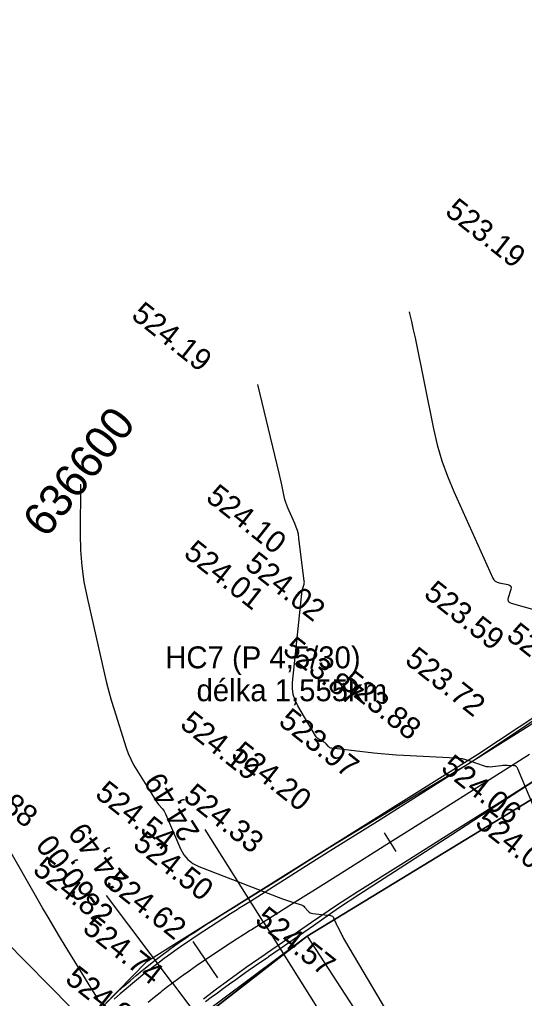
# Model space of a CAD drawing. Extents: x -636600 to -628587, y -1090963 to -1085869.
# Drawn here: x -629781.6 to -629735.5, y -1089769.7 to -1089680.4 of the extents above; entities that cross this region are included whole.
import ezdxf

# ---------------------------------------------------------------- set-up
doc = ezdxf.new("R2010")
doc.units = 0
for name, color, linetype in [('01_PARCELY_NÁVRH_PC', 7, 'Continuous'), ('21', 7, 'Continuous'), ('23', 7, 'Continuous'), ('Ex_Major Contours', 7, 'Continuous'), ('Ex_Minor Contours', 7, 'Continuous'), ('HEKTOMETRY100', 7, 'Continuous'), ('HEKTOMETRY20', 7, 'Continuous'), ('HL_BODY', 7, 'Continuous'), ('koty_vše', 7, 'Continuous'), ('PARCELY_NÁVRH_SILNICE_ŽELEZNICE', 7, 'Continuous'), ('POLOMERY', 7, 'Continuous'), ('popis', 7, 'Continuous'), ('situace_osa', 7, 'Continuous'), ('situace_těleso', 7, 'Continuous'), ('situace_vozovka', 7, 'Continuous'), ('síť křížků', 7, 'Continuous'), ('VRCHOLY', 7, 'Continuous')]:
    doc.layers.add(name, color=color, linetype=linetype)

msp = doc.modelspace()

# ---------------------------------------------------------------- linework, layer by layer
at = {"layer": '01_PARCELY_NÁVRH_PC'}
msp.add_lwpolyline([(-629647.363, -1089680.417), (-629666.288, -1089692.668), (-629711.76, -1089728.929), (-629739.767, -1089747.431), (-629770.066, -1089766.37), (-629781.624, -1089778.209), (-629800.275, -1089807.802), (-629798.048, -1089809.483), (-629791.307, -1089814.356), (-629789.014, -1089815.993), (-629775.661, -1089789.328), (-629773.774, -1089778.258), (-629755.349, -1089764.02), (-629715.944, -1089740.02), (-629693.039, -1089722.565), (-629669.229, -1089703.189), (-629636.498, -1089682.368)], dxfattribs=at)
at = {"layer": '21'}
for p, q in [((-629715.944, -1089740.02), (-629755.349, -1089764.02)), ((-629755.349, -1089764.02), (-629773.469, -1089777.492))]:
    msp.add_line(p, q, dxfattribs=at)
at = {"layer": '23'}
for p, q in [((-629773.774, -1089778.258), (-629755.349, -1089764.02)), ((-629755.349, -1089764.02), (-629745.662, -1089778.847))]:
    msp.add_line(p, q, dxfattribs=at)
at = {"layer": 'Ex_Major Contours'}
msp.add_lwpolyline([(-629774.482, -1089769.733), (-629777.454, -1089764.884), (-629777.978, -1089764.022), (-629778.495, -1089763.156), (-629779.006, -1089762.286), (-629779.51, -1089761.412), (-629783.136, -1089755.074)], dxfattribs=at)
at = {"layer": 'Ex_Minor Contours'}
for points in [[(-629746.032, -1089707.072), (-629746, -1089707.207), (-629745.83, -1089707.954), (-629745.667, -1089708.703), (-629745.51, -1089709.453), (-629743.818, -1089717.743), (-629743.476, -1089719.211), (-629743.053, -1089720.652), (-629742.551, -1089722.068), (-629741.97, -1089723.458), (-629738.405, -1089731.35), (-629738.307, -1089731.516), (-629738.181, -1089731.645), (-629738.025, -1089731.737), (-629737.84, -1089731.792), (-629737.034, -1089731.941), (-629736.871, -1089731.996), (-629736.772, -1089732.089), (-629736.737, -1089732.22), (-629736.766, -1089732.389), (-629737.008, -1089733.142), (-629737.037, -1089733.313), (-629737.004, -1089733.451), (-629736.907, -1089733.555), (-629736.748, -1089733.625), (-629729.613, -1089735.629)], [(-629734.308, -1089753.082), (-629736.118, -1089748.738), (-629736.183, -1089748.622), (-629736.271, -1089748.538), (-629736.38, -1089748.485), (-629736.511, -1089748.463), (-629737.079, -1089748.438), (-629737.221, -1089748.435), (-629737.363, -1089748.438), (-629737.504, -1089748.447), (-629737.645, -1089748.463), (-629738.45, -1089748.571), (-629738.631, -1089748.585), (-629738.808, -1089748.578), (-629738.984, -1089748.55), (-629739.158, -1089748.5), (-629740.577, -1089748.007), (-629740.873, -1089747.915), (-629741.173, -1089747.846), (-629741.478, -1089747.797), (-629741.787, -1089747.771), (-629746.565, -1089747.53), (-629747.241, -1089747.491), (-629747.915, -1089747.441), (-629748.589, -1089747.38), (-629749.262, -1089747.308), (-629753.128, -1089746.866), (-629753.209, -1089746.85), (-629753.282, -1089746.82), (-629753.349, -1089746.777), (-629753.409, -1089746.721), (-629753.634, -1089746.469), (-629753.692, -1089746.409), (-629753.755, -1089746.354), (-629753.822, -1089746.304), (-629753.893, -1089746.26), (-629754.293, -1089746.032), (-629754.379, -1089745.975), (-629754.456, -1089745.909), (-629754.524, -1089745.833), (-629754.582, -1089745.747), (-629756.216, -1089742.987), (-629756.463, -1089742.488), (-629756.623, -1089741.969), (-629756.696, -1089741.431), (-629756.682, -1089740.874), (-629755.856, -1089732.75), (-629755.843, -1089732.654), (-629755.826, -1089732.558), (-629755.804, -1089732.463), (-629755.776, -1089732.37), (-629755.657, -1089731.998), (-629755.632, -1089731.904), (-629755.618, -1089731.81), (-629755.614, -1089731.714), (-629755.621, -1089731.618), (-629756.105, -1089727.702), (-629756.161, -1089727.358), (-629756.241, -1089727.022), (-629756.348, -1089726.692), (-629756.479, -1089726.369), (-629757.119, -1089724.953), (-629757.224, -1089724.701), (-629757.315, -1089724.445), (-629757.391, -1089724.184), (-629757.453, -1089723.918), (-629757.672, -1089722.847), (-629757.728, -1089722.579), (-629757.786, -1089722.312), (-629757.847, -1089722.046), (-629757.91, -1089721.78), (-629759.86, -1089713.707)], [(-629776.041, -1089722.79), (-629776.079, -1089727.338), (-629776.049, -1089728.8), (-629775.934, -1089730.253), (-629775.736, -1089731.696), (-629775.453, -1089733.13), (-629773.865, -1089740.124), (-629773.676, -1089740.915), (-629773.471, -1089741.7), (-629773.249, -1089742.482), (-629773.01, -1089743.258), (-629771.875, -1089746.816), (-629771.685, -1089747.353), (-629771.462, -1089747.874), (-629771.208, -1089748.381), (-629770.921, -1089748.873), (-629769.245, -1089751.552), (-629769.172, -1089751.664), (-629769.095, -1089751.773), (-629769.014, -1089751.88), (-629768.929, -1089751.983), (-629768.58, -1089752.39), (-629768.497, -1089752.495), (-629768.423, -1089752.604), (-629768.357, -1089752.72), (-629768.3, -1089752.84), (-629766.918, -1089756.044), (-629766.628, -1089756.576), (-629766.254, -1089757.02), (-629765.795, -1089757.377), (-629765.254, -1089757.647), (-629757.623, -1089760.604), (-629757.44, -1089760.673), (-629757.255, -1089760.737), (-629757.069, -1089760.798), (-629756.881, -1089760.854), (-629755.986, -1089761.112), (-629755.872, -1089761.153), (-629755.768, -1089761.209), (-629755.673, -1089761.279), (-629755.587, -1089761.363), (-629755.26, -1089761.728), (-629755.174, -1089761.81), (-629755.077, -1089761.872), (-629754.97, -1089761.915), (-629754.854, -1089761.938), (-629753.221, -1089762.125), (-629753.131, -1089762.146), (-629753.055, -1089762.187), (-629752.993, -1089762.248), (-629752.947, -1089762.328), (-629752.789, -1089762.688), (-629752.749, -1089762.778), (-629752.708, -1089762.868), (-629752.666, -1089762.957), (-629752.624, -1089763.046), (-629752.267, -1089763.779), (-629752.191, -1089763.929), (-629752.113, -1089764.079), (-629752.032, -1089764.226), (-629751.947, -1089764.372), (-629745.083, -1089775.97)]]:
    msp.add_lwpolyline(points, dxfattribs=at)
at = {"layer": 'HEKTOMETRY100'}
msp.add_lwpolyline([(-629763.521, -1089767.807), (-629765.762, -1089764.494)], dxfattribs=at)
at = {"layer": 'HEKTOMETRY20'}
msp.add_lwpolyline([(-629747.22, -1089756.284), (-629748.286, -1089754.592)], dxfattribs=at)
at = {"layer": 'HL_BODY'}
for points in [[(-629759.344, -1089762.734), (-629754.017, -1089771.197)], [(-629767.653, -1089768.292), (-629761.641, -1089776.282)]]:
    msp.add_lwpolyline(points, dxfattribs=at)
at = {"layer": 'PARCELY_NÁVRH_SILNICE_ŽELEZNICE'}
msp.add_lwpolyline([(-629636.498, -1089682.368), (-629669.229, -1089703.189), (-629693.039, -1089722.565), (-629715.944, -1089740.02), (-629755.349, -1089764.02), (-629773.774, -1089778.258), (-629775.661, -1089789.328), (-629789.014, -1089815.993), (-629763.271, -1089834.375), (-629762.496, -1089834.892), (-629746.798, -1089807.362), (-629739.641, -1089797.354), (-629724.72, -1089773.793), (-629704.711, -1089750.564), (-629683.036, -1089730.713), (-629659.95, -1089713.109)], dxfattribs=at)
at = {"layer": 'POLOMERY'}
for points in [[(-629759.344, -1089762.734), (-629764.671, -1089754.271)], [(-629767.653, -1089768.292), (-629773.666, -1089760.302)]]:
    msp.add_lwpolyline(points, dxfattribs=at)
at = {"layer": 'situace_osa'}
msp.add_lwpolyline([(-629735.058, -1089747.448), (-629739.29, -1089750.111), (-629743.521, -1089752.775), (-629747.753, -1089755.438), (-629751.984, -1089758.101), (-629753.876, -1089759.292), (-629756.216, -1089760.765), (-629759.344, -1089762.734), (-629759.949, -1089763.115), (-629760.447, -1089763.429), (-629760.553, -1089763.496), (-629761.156, -1089763.878), (-629761.759, -1089764.261), (-629762.36, -1089764.647), (-629762.959, -1089765.035), (-629763.557, -1089765.427), (-629764.152, -1089765.822), (-629764.641, -1089766.15), (-629764.745, -1089766.22), (-629765.334, -1089766.624), (-629765.92, -1089767.032), (-629766.476, -1089767.427), (-629766.502, -1089767.446), (-629767.08, -1089767.866), (-629767.653, -1089768.292), (-629768.218, -1089768.722), (-629768.687, -1089769.087), (-629768.778, -1089769.159), (-629769.332, -1089769.603), (-629769.881, -1089770.053)], dxfattribs=at)
at = {"layer": 'situace_těleso'}
for points in [[(-629773.694, -1089770.086), (-629773.174, -1089769.559), (-629772.637, -1089769.049), (-629772.09, -1089768.55), (-629771.53, -1089768.065), (-629770.965, -1089767.587), (-629770.393, -1089767.115), (-629770.299, -1089767.039), (-629769.815, -1089766.651), (-629769.232, -1089766.195), (-629768.64, -1089765.743), (-629768.044, -1089765.301), (-629768.017, -1089765.281), (-629767.445, -1089764.866), (-629766.841, -1089764.442), (-629766.231, -1089764.031), (-629766.124, -1089763.959), (-629765.619, -1089763.626), (-629765.007, -1089763.227), (-629764.393, -1089762.833), (-629763.78, -1089762.444), (-629763.166, -1089762.059), (-629762.555, -1089761.675), (-629761.944, -1089761.294), (-629761.837, -1089761.228), (-629761.334, -1089760.916), (-629760.725, -1089760.54), (-629757.578, -1089758.601), (-629755.243, -1089757.12), (-629753.355, -1089755.924), (-629749.074, -1089753.34), (-629744.787, -1089750.764), (-629740.493, -1089748.199), (-629736.33, -1089745.428), (-629732.185, -1089742.626)], [(-629733.851, -1089749.366), (-629738.042, -1089752.093), (-629742.234, -1089754.82), (-629746.431, -1089757.538), (-629750.634, -1089760.248), (-629752.507, -1089761.466), (-629754.767, -1089763.067), (-629757.812, -1089765.169), (-629758.401, -1089765.57), (-629758.886, -1089765.901), (-629758.989, -1089765.971), (-629759.573, -1089766.371), (-629760.155, -1089766.771), (-629760.733, -1089767.172), (-629761.307, -1089767.573), (-629761.877, -1089767.976), (-629762.443, -1089768.38), (-629762.906, -1089768.716), (-629763.003, -1089768.787), (-629763.559, -1089769.195), (-629764.108, -1089769.607), (-629764.627, -1089770.003)]]:
    msp.add_lwpolyline(points, dxfattribs=at)
at = {"layer": 'situace_vozovka'}
for points in [[(-629732.025, -1089742.88), (-629736.257, -1089745.543), (-629740.488, -1089748.207), (-629744.72, -1089750.87), (-629748.951, -1089753.534), (-629753.183, -1089756.197), (-629755.075, -1089757.388), (-629757.415, -1089758.861), (-629760.543, -1089760.83), (-629761.148, -1089761.211), (-629761.648, -1089761.526), (-629761.755, -1089761.593), (-629762.362, -1089761.978), (-629762.97, -1089762.365), (-629763.579, -1089762.756), (-629764.187, -1089763.15), (-629764.795, -1089763.548), (-629765.402, -1089763.951), (-629765.902, -1089764.287), (-629766.008, -1089764.359), (-629766.613, -1089764.772), (-629767.215, -1089765.192), (-629767.788, -1089765.599), (-629767.815, -1089765.619), (-629768.412, -1089766.053), (-629769.006, -1089766.494), (-629769.592, -1089766.941), (-629770.078, -1089767.319), (-629770.173, -1089767.394), (-629770.748, -1089767.854), (-629771.318, -1089768.321), (-629771.882, -1089768.795), (-629772.44, -1089769.275), (-629772.993, -1089769.762)], [(-629732.025, -1089742.88), (-629736.257, -1089745.543), (-629740.488, -1089748.207), (-629744.72, -1089750.87), (-629748.951, -1089753.534), (-629753.183, -1089756.197), (-629755.075, -1089757.388), (-629757.415, -1089758.861), (-629760.543, -1089760.83), (-629761.148, -1089761.211), (-629761.648, -1089761.526), (-629761.755, -1089761.593), (-629762.362, -1089761.978), (-629762.97, -1089762.365), (-629763.579, -1089762.756), (-629764.187, -1089763.15), (-629764.795, -1089763.548), (-629765.402, -1089763.951), (-629765.902, -1089764.287), (-629766.008, -1089764.359), (-629766.613, -1089764.772), (-629767.215, -1089765.192), (-629767.788, -1089765.599), (-629767.815, -1089765.619), (-629768.412, -1089766.053), (-629769.006, -1089766.494), (-629769.592, -1089766.941), (-629770.078, -1089767.319), (-629770.173, -1089767.394), (-629770.748, -1089767.854), (-629771.318, -1089768.321), (-629771.882, -1089768.795), (-629772.44, -1089769.275), (-629772.993, -1089769.762)], [(-629733.86, -1089749.352), (-629738.091, -1089752.015), (-629742.323, -1089754.679), (-629746.554, -1089757.342), (-629750.786, -1089760.006), (-629752.677, -1089761.196), (-629754.958, -1089762.763), (-629758.008, -1089764.857), (-629758.596, -1089765.261), (-629759.08, -1089765.594), (-629759.182, -1089765.665), (-629759.766, -1089766.068), (-629760.347, -1089766.472), (-629760.924, -1089766.876), (-629761.497, -1089767.281), (-629762.067, -1089767.688), (-629762.632, -1089768.097), (-629763.094, -1089768.437), (-629763.192, -1089768.509), (-629763.747, -1089768.923), (-629764.296, -1089769.341), (-629764.814, -1089769.743)], [(-629733.86, -1089749.352), (-629738.091, -1089752.015), (-629742.323, -1089754.679), (-629746.554, -1089757.342), (-629750.786, -1089760.006), (-629752.677, -1089761.196), (-629754.958, -1089762.763), (-629758.008, -1089764.857), (-629758.596, -1089765.261), (-629759.08, -1089765.594), (-629759.182, -1089765.665), (-629759.766, -1089766.068), (-629760.347, -1089766.472), (-629760.924, -1089766.876), (-629761.497, -1089767.281), (-629762.067, -1089767.688), (-629762.632, -1089768.097), (-629763.094, -1089768.437), (-629763.192, -1089768.509), (-629763.747, -1089768.923), (-629764.296, -1089769.341), (-629764.814, -1089769.743)]]:
    msp.add_lwpolyline(points, dxfattribs=at)
at = {"layer": 'VRCHOLY'}
msp.add_lwpolyline([(-629774.912, -1089772.533), (-629788.994, -1089758.331)], dxfattribs=at)

# ---------------------------------------------------------------- texts
at = {"layer": 'koty_vše'}
for s, p in [('523.19', (-629742.87, -1089698.114)), ('524.19', (-629771.517, -1089707.573)), ('524.10', (-629764.713, -1089724.201)), ('524.01', (-629766.733, -1089729.295)), ('524.02', (-629761.166, -1089730.35)), ('523.59', (-629744.815, -1089732.984)), ('523.69', (-629737.282, -1089736.813)), ('523.87', (-629757.693, -1089738.083)), ('523.72', (-629746.545, -1089739.033)), ('523.88', (-629752.403, -1089741.162)), ('524.19', (-629767.075, -1089744.871)), ('523.97', (-629758.08, -1089744.631)), ('524.20', (-629762.422, -1089747.65)), ('524.88', (-629787.409, -1089749.157)), ('524.06', (-629743.252, -1089748.853)), ('524.54', (-629774.824, -1089751.239)), ('524.33', (-629766.778, -1089751.487)), ('524.04', (-629740.13, -1089753.864)), ('524.50', (-629771.375, -1089755.833)), ('524.82', (-629780.51, -1089758.154)), ('524.62', (-629773.847, -1089759.373)), ('524.57', (-629760.235, -1089762.712)), ('524.74', (-629775.971, -1089763.493)), ('524.93', (-629777.561, -1089768.111))]:
    msp.add_text(s, height=2, rotation=321.72649, dxfattribs=at).set_placement(p)
at = {"layer": 'POLOMERY'}
for s, rotation, p in [('24,49', 122.1878, (-629765.094, -1089754.537)), ('24,49', 126.96245, (-629771.669, -1089758.799)), ('-60,00', 126.96245, (-629774.066, -1089760.603))]:
    msp.add_text(s, height=2, rotation=rotation, dxfattribs=at).set_placement(p)
at = {"layer": 'popis'}
for s, p in [('HC7 (P 4,5/30)', (-629768.314, -1089739.58)), ('délka 1,555km', (-629765.457, -1089742.58))]:
    msp.add_text(s, height=2, dxfattribs=at).set_placement(p)
at = {"layer": 'síť křížků'}
msp.add_text('636600', height=3, rotation=51.72649, dxfattribs=at).set_placement((-629779.193, -1089727.806))

doc.saveas('drawing.dxf')
